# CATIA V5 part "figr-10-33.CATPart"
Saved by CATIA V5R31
Part number: Part1
Bounding box of the stored display mesh (mm): x -193.573 to 205.258, y -140.014 to 12.054, z -96.593 to 19.319
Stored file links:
  D:\PROJECTS\Project 2021\US EDITION\CATIA V5 6R 2021\Resources\Part Files\c10_catia_v5_6r2021_prt\c10_catia_v5_6r2021_prt\figr-10-33.CATPart
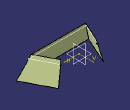
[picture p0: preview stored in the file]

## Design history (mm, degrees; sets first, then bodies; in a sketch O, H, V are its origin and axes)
Body1 (main body)
  Sketch1 on xy-plane, origin (0, 0, 0), H (1, 0, 0), V (0, 1, 0)
    line L1 (-101.4744, 0) -> (-153.3719, -114.1323)
    point P1 (-101.4744, 0)
    line L2 (-153.3719, -114.1323) -> (162.3879, -114.1323)
    line L3 (162.3879, -114.1323) -> (102.3183, 0)
    point P4 (102.3183, 0)
    coincidence: P1 H, P4 H
    horizontal: L2 H
  Sweep1: type Segment, GuideCrv Sketch1, Length1 20, Length2 100, Angle 15, DraftDirection xy-plane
